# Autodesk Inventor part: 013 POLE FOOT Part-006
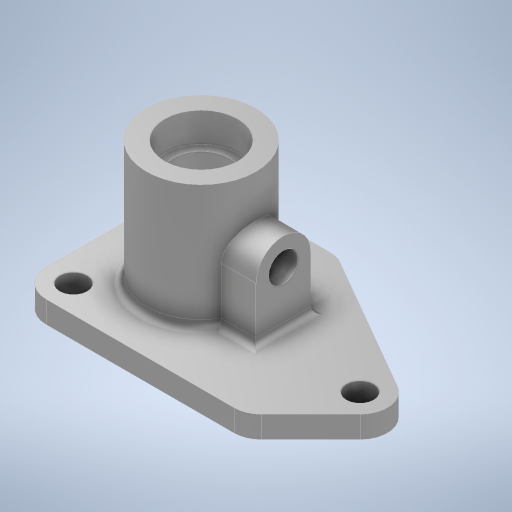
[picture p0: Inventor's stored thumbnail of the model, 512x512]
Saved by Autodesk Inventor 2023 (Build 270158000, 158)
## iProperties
Created: 2022-06
Part Number: 013 POLE FOOT Part-006
Material: Steel, Carbon
Document SubType Name: Modeling
Designer: Usuario
Density: 7.85 g/cm^3
Appearance: Gunmetal - Polished
Author: Usuario
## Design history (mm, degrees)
sketch "Sketch1"
  geometry: L1 (50, -50)-(50, 50); L2 (50, 50)-(-74.213, 50); L3 (-74.213, 50)-(-105.607, 18.607); L4 (-102.5, -4.99)-(-24.541, -50); L5 (-24.541, -50)-(50, -50); A1 r 15 centre (-95, 8) between (-105.607, 18.607) and (-102.5, -4.99); 2 further points
  constraints: 10 end point, 2 point on circle, 2 tangent, 1 centre point, 1 horizontal alignment, 1 midpoint, 1 parallel, 1 perpendicular, 1 vertical
  dimensions: "d0" = 15 radius of A1 (derived); "d1" = 145 distance from line of L1 A1.centre; "d2" = 100 distance between parallel lines of L2 L5; "d3" = 135 deg angle of L3 L2; "d4" = 30 deg angle of L4 L5; "d5" = 42 distance from line of L2 A1.centre; "d6" = 50 distance of L1.end point (50, 0) (derived); "d7" = 50 distance from line of point (0, 0) L1
extrude "Extrusion1" new body sketch "Sketch1" distance "d8" = 12; taper "d9" = 0 deg
fillet "Fillet1" dims "d10" = 15
sketch "Sketch2"
  geometry: C1 r 30 at (0, 0); 1 further point
  constraints: 1 centre point, 1 coincident
  dimensions: "d11" = 60 diameter of C1
extrude "Extrusion2" join sketch "Sketch2" distance "d12" = 68; taper "d13" = 0 deg
workplane "Work Plane1"
sketch "Sketch3"
  geometry: L1 (12, 30)-(12, -30) reference; L2 (12, -4.99)-(12, 18.607) reference; L3 (12, 15)-(42, 15); L4 (-16, 0)-(96, 0) reference; L5 (12, -15)-(42, -15); L6 (12, -15)-(12, 15); L7 (12, -35)-(12, 35) reference; A1 r 15 centre (42, 0) between (57, 0) and (42, 15); A2 r 15 centre (42, 0) between (42, -15) and (57, 0); 2 further points
  constraints: 6 end point, 4 point on circle, 3 point on line, 2 centre point, 2 symmetric about line, 1 collinear, 1 perpendicular, 1 tangent, 1 other
  dimensions: "d15" = 15 radius of A1; "d16" = 42 distance of point (0, 0) A1.centre
extrude "Extrusion3" join sketch "Sketch3" stored distance "d17" = 68; taper "d18" = 0 deg
sketch "Sketch4"
  geometry: C1 r 30 at (0, 0) reference; 2 further points
  constraints: 1 coincident
hole "Hole1" sketch "Sketch4" at (0, 0) diameter "d19" = 30; stored, may be unused: countersink angle "d23" = 90 deg, drill point angle "d25" = 0 deg; dims "d20" = 16, "d21" = 40, "d22" = 16, "d24" = 127.5
sketch "Sketch5"
  geometry: A1 r 15 centre (0, 42) between (15, 42) and (-15, 42) reference; 2 further points
  constraints: 1 coincident
hole "Hole2" sketch "Sketch5" at (0, 42) diameter "d26" = 16; stored, may be unused: countersink angle "d30" = 90 deg, drill point angle "d32" = 0 deg; dims "d27" = 6, "d28" = 40, "d29" = 16, "d31" = 64
sketch "Sketch6"
  geometry: A1 r 15 centre (-35, -35) between (-50, -35) and (-35, -50) reference; A2 r 15 centre (95, -8) between (105.607, -18.607) and (102.5, 4.99) reference; A3 r 15 centre (-35, 35) between (-35, 50) and (-50, 35) reference
hole "Hole3" sketch "Sketch6" at (-35, 35), (-35, -35), (95, -8) diameter "d33" = 15; stored, may be unused: countersink angle "d37" = 90 deg, drill point angle "d39" = 0 deg; dims "d34" = 6, "d35" = 40, "d36" = 16, "d38" = 127.5
fillet "Fillet2" dims "d40" = 4
body "Solid1"
other parameters: "d14" = 45
